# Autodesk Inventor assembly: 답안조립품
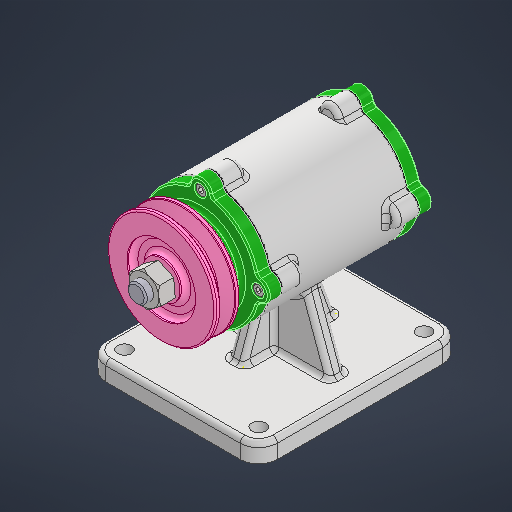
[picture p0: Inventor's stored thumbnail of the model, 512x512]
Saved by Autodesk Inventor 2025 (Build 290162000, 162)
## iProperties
Created: 2025-08
Part Number: 답안조립품
Document SubType Name: Assembly
Designer: infra012
Author: infra012
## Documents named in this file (12)
- C:\Users\infra012\Desktop\750806V1002\답안조립품.iam
- C:\Users\infra012\Desktop\750806V1002\V-벨트풀리\V-벨트풀리.ipt
- C:\Users\infra012\Desktop\750806V1002\개스킷\개스킷.ipt
- C:\Users\infra012\Desktop\750806V1002\너트 M12 x 1.25\너트 M12 x 1.25.ipt
- C:\Users\infra012\Desktop\750806V1002\뒤커버\뒤커버.ipt
- C:\Users\infra012\Desktop\750806V1002\베어링 6204\베어링 6204.ipt
- C:\Users\infra012\Desktop\750806V1002\볼트 M4 x 12\볼트 M4 x 12.ipt
- C:\Users\infra012\Desktop\750806V1002\앞커버\앞커버.ipt
- C:\Users\infra012\Desktop\750806V1002\오일 실\오일 실.ipt
- C:\Users\infra012\Desktop\750806V1002\축\축.ipt
- C:\Users\infra012\Desktop\750806V1002\키 4 x 4\키 4 x 4.ipt
- C:\Users\infra012\Desktop\750806V1002\본체.ipt
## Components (3 placed, 2 different names)
1. V-벨트풀리:1
2. 개스킷:1
3. 개스킷:2
